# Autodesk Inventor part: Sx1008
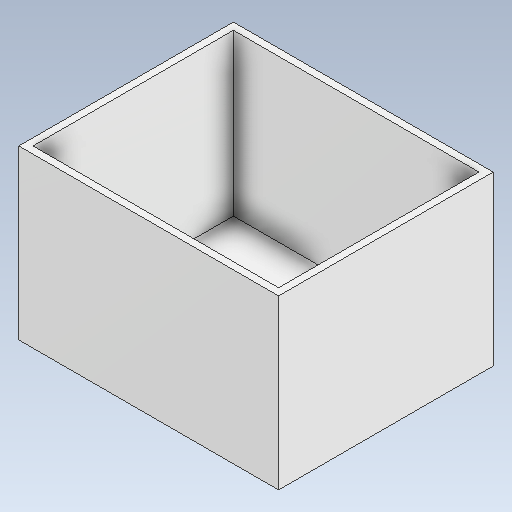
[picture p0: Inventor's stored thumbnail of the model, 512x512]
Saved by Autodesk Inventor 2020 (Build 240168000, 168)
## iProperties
Created: 2021-02
Part Number: Sx1008
Material: Generico
Document SubType Name: Modeling
Designer: zambolin
Density: 1 g/cm^3
Appearance: Default
Author: zambolin
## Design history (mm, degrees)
feature "Solido2"
node "Solido1"
